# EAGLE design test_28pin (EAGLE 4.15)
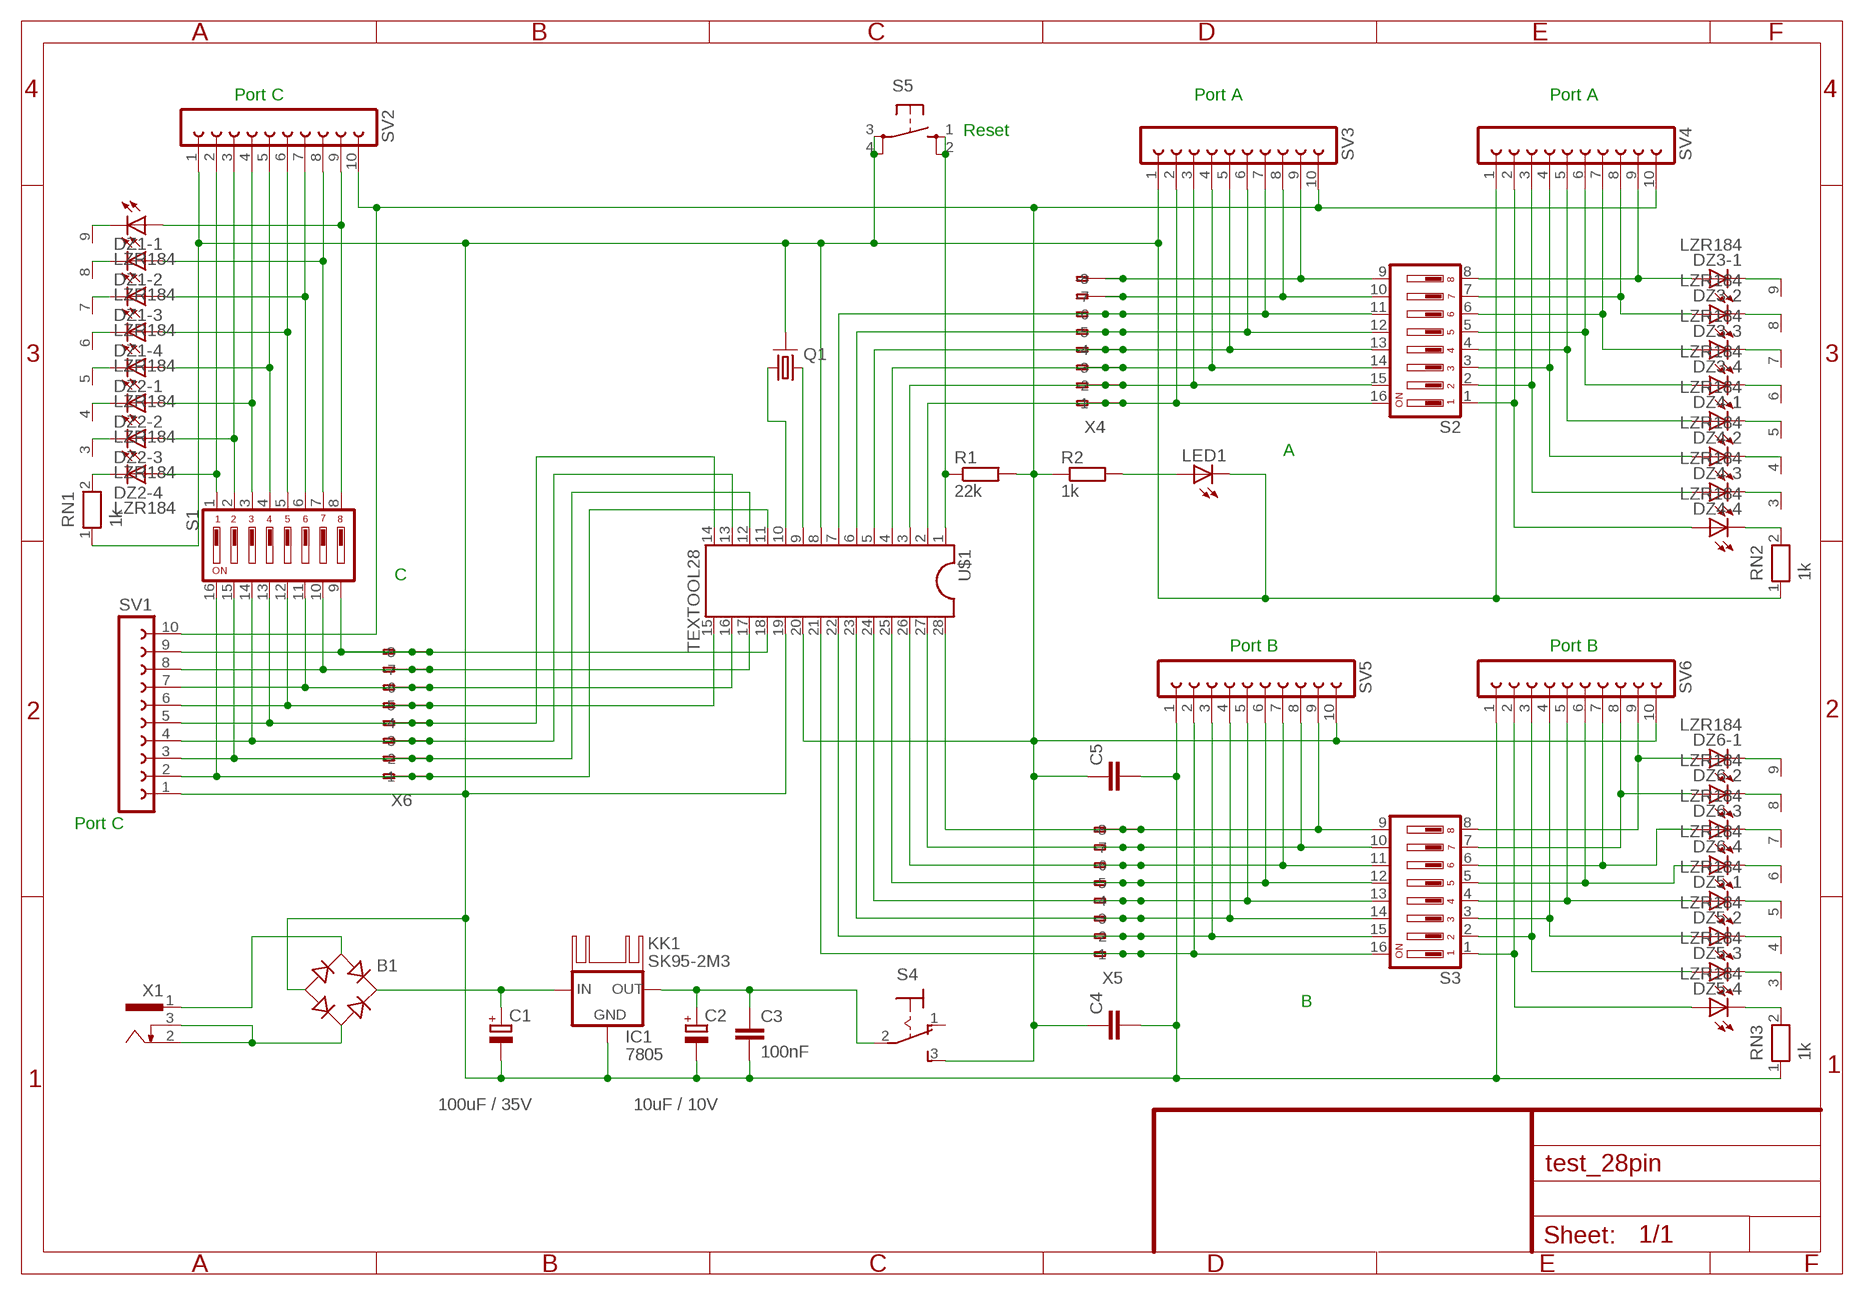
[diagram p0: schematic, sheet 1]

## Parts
B1  RB1A  [RB1A]
C1  100uF / 35V  CPOL-EUE2.5-5  [E2,5-5]
C2  10uF / 10V  CPOL-EUE2.5-5  [E2,5-5]
C3  100nF  C-EU025-024X044  [C025-024X044]
C4  C-EU050-025X075  [C050-025X075]
C5  C-EU050-025X075  [C050-025X075]
DZ1  LZR184  [LZR184]
DZ2  LZR184  [LZR184]
DZ3  LZR184  [LZR184]
DZ4  LZR184  [LZR184]
DZ5  LZR184  [LZR184]
DZ6  LZR184  [LZR184]
IC1  7805  78XXS  [78XXS]
KK1  SK95-2M3  [SK95-2M3]
LED1  LED3MM  [LED3MM]
Q1  RESONATOR  [RES3PIN]
R1  22k  R-EU_0207/15  [0207/15]
R2  1k  R-EU_0207/10  [0207/10]
RN1  1k  RN08  [RN-9]
RN2  1k  RN08  [RN-9]
RN3  1k  RN08  [RN-9]
S1  DS08  [DS-08]
S2  DS08  [DS-08]
S3  DS08  [DS-08]
S4  320-916  [320-916]
S5  10XX  [B3F-10XX]
SV1  FE10-1  [FE10]
SV2  FE10-1  [FE10]
SV3  FE10-1  [FE10]
SV4  FE10-1  [FE10]
SV5  FE10-1  [FE10]
SV6  FE10-1  [FE10]
U$1  TEXTOOL28  [TEXTOOL28]
X1  733989-55  [733989-5]
X4  233-508  [233-508]
X5  233-508  [233-508]
X6  233-508  [233-508]

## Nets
N$1: S3.16 SV5.2 U$1.21 X5.A1(-1) X5.B1(B-1)
N$2: S3.15 SV5.3 U$1.22 X5.A2(-2) X5.B2(B-2)
N$3: S3.14 SV5.4 U$1.23 X5.A3(-3) X5.B3(B-3)
N$4: S3.13 SV5.5 U$1.24 X5.A4(-4) X5.B4(B-4)
N$5: S3.12 SV5.6 U$1.25 X5.A5(-5) X5.B5(B-5)
N$6: S3.11 SV5.7 U$1.26 X5.A6(-6) X5.B6(B-6)
N$7: S3.10 SV5.8 U$1.27 X5.A7(-7) X5.B7(B-7)
N$8: S3.9 SV5.9 U$1.28 X5.A8(-8) X5.B8(B-8)
N$9: DZ6.A1(-1:A) S3.8 SV6.9
N$10: DZ6.A2(-2:A) S3.7 SV6.8
N$11: DZ6.A3(-3:A) S3.6 SV6.7
N$12: DZ6.A4(-4:A) S3.5 SV6.6
N$13: DZ5.A1(-1:A) S3.4 SV6.5
N$14: DZ5.A2(-2:A) S3.3 SV6.4
N$15: DZ5.A3(-3:A) S3.2 SV6.3
N$16: DZ5.A4(-4:A) S3.1 SV6.2
N$17: DZ6.K4(-4:C) RN3.6
N$18: DZ6.K1(-1:C) RN3.9
N$19: DZ6.K2(-2:C) RN3.8
N$20: DZ6.K3(-3:C) RN3.7
N$21: DZ5.K4(-4:C) RN3.2
N$22: DZ5.K1(-1:C) RN3.5
N$23: DZ5.K2(-2:C) RN3.4
N$24: DZ5.K3(-3:C) RN3.3
N$25: C4.1 C5.1 R1.2 R2.1 S4.3(S) SV1.10 SV2.10 SV3.10 SV4.10 SV5.10 SV6.10 U$1.20
N$26: LED1.A R2.2
N$27: DZ3.K1(-1:C) RN2.9
N$28: DZ3.K2(-2:C) RN2.8
N$29: DZ3.K3(-3:C) RN2.7
N$30: DZ3.K4(-4:C) RN2.6
N$31: DZ4.K1(-1:C) RN2.5
N$32: DZ4.K2(-2:C) RN2.4
N$33: DZ4.K3(-3:C) RN2.3
N$34: DZ4.K4(-4:C) RN2.2
N$35: S2.9 SV3.9 X4.A8(-8) X4.B8(B-8)
N$36: S2.10 SV3.8 X4.A7(-7) X4.B7(B-7)
N$37: S2.11 SV3.7 U$1.7 X4.A6(-6) X4.B6(B-6)
N$38: S2.12 SV3.6 U$1.6 X4.A5(-5) X4.B5(B-5)
N$39: S2.13 SV3.5 U$1.5 X4.A4(-4) X4.B4(B-4)
N$40: Q1.3 U$1.9
N$41: S2.15 SV3.3 U$1.3 X4.A2(-2) X4.B2(B-2)
N$42: S2.16 SV3.2 U$1.2 X4.A1(-1) X4.B1(B-1)
N$43: DZ4.A4(-4:A) S2.1 SV4.2
N$44: DZ4.A3(-3:A) S2.2 SV4.3
N$45: DZ4.A2(-2:A) S2.3 SV4.4
N$46: DZ4.A1(-1:A) S2.4 SV4.5
N$47: DZ3.A4(-4:A) S2.5 SV4.6
N$48: DZ3.A3(-3:A) S2.6 SV4.7
N$49: DZ3.A2(-2:A) S2.7 SV4.8
N$50: S1.9 SV1.9 U$1.18 X6.A8(-8) X6.B8(B-8)
N$51: DZ3.A1(-1:A) S2.8 SV4.9
N$54: DZ1.K1(-1:C) RN1.9
N$55: DZ1.K2(-2:C) RN1.8
N$56: DZ1.K3(-3:C) RN1.7
N$57: DZ1.K4(-4:C) RN1.6
N$58: DZ2.K1(-1:C) RN1.5
N$59: DZ2.K2(-2:C) RN1.4
N$60: DZ2.K3(-3:C) RN1.3
N$61: DZ2.K4(-4:C) RN1.2
N$62: DZ1.A1(-1:A) S1.8 SV2.9
N$63: DZ1.A2(-2:A) S1.7 SV2.8
N$64: DZ1.A3(-3:A) S1.6 SV2.7
N$65: DZ1.A4(-4:A) S1.5 SV2.6
N$66: DZ2.A1(-1:A) S1.4 SV2.5
N$67: DZ2.A2(-2:A) S1.3 SV2.4
N$68: DZ2.A3(-3:A) S1.2 SV2.3
N$69: DZ2.A4(-4:A) S1.1 SV2.2
N$70: S1.10 SV1.8 U$1.17 X6.A7(-7) X6.B7(B-7)
N$71: S1.11 SV1.7 U$1.16 X6.A6(-6) X6.B6(B-6)
N$72: S1.12 SV1.6 U$1.15 X6.A5(-5) X6.B5(B-5)
N$73: S1.13 SV1.5 U$1.14 X6.A4(-4) X6.B4(B-4)
N$74: S1.14 SV1.4 U$1.13 X6.A3(-3) X6.B3(B-3)
N$75: S1.15 SV1.3 U$1.12 X6.A2(-2) X6.B2(B-2)
N$76: S1.16 SV1.2 U$1.11 X6.A1(-1) X6.B1(B-1)
N$77: Q1.1 U$1.10
N$78: S2.14 SV3.4 U$1.4 X4.A3(-3) X4.B3(B-3)
N$81: B1.+ C1.+ IC1.IN
N$84: B1.AC2 X1.2 X1.3
N$85: B1.AC1 X1.1
N$86: R1.1 S5.1 S5.2 U$1.1
N$88: C2.+ C3.1 IC1.OUT S4.2(P)
VSS: B1.- C1.- C2.- C3.2 C4.2 C5.2 IC1.GND LED1.K(C) Q1.2 RN1.1 RN2.1 RN3.1 S5.3 S5.4 SV1.1 SV2.1 SV3.1 SV4.1 SV5.1 SV6.1 U$1.8 U$1.19
Unconnected: S4.1(O)

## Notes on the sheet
- Port C | Port A | Port A
- Reset
- A
- C
- Port B | Port B
- Port C
- B

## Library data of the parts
B1 = rectifier:RB1A: RECTIFIER 1 A
C1 C2 = rcl:CPOL-EU: POLARIZED CAPACITOR, European symbol
C3-C5 = rcl:C-EU: CAPACITOR, European symbol
DZ1-DZ6 = led:LZR184: LED BLOCK 4 LEDs, Siemens
IC1 = v-reg:78XXS: VOLTAGE REGULATOR
KK1 = heatsink:SK95-2M3: HEATSINK
LED1 = led:LED: LED
Q1 = sprut:RESONATOR: CRYSTAL
R1 R2 = rcl:R-EU_: RESISTOR, European symbol
RN1-RN3 = resistor-net:RN08: RESISTOR NETWORK
S1-S3 = switch-dil:DS08: DIL/CODE SWITCH
S4 = switch:320-916: TOGGLE SWITCH distributor RS Components
S5 = KEY_B:10XX
SV1-SV6 = con-lsta:FE10-1: FEMALE HEADER
U$1 = sprut:TEXTOOL28
X1 = con-conrad:733989-55: FEMALE PRINT CONNECTOR Außen-Ø 4,2 mm, Innen 1.1 mm FUK HING Industries, distributor Conrad
X4-X6 = con-wago:233-508: WAGO Cage Clamp

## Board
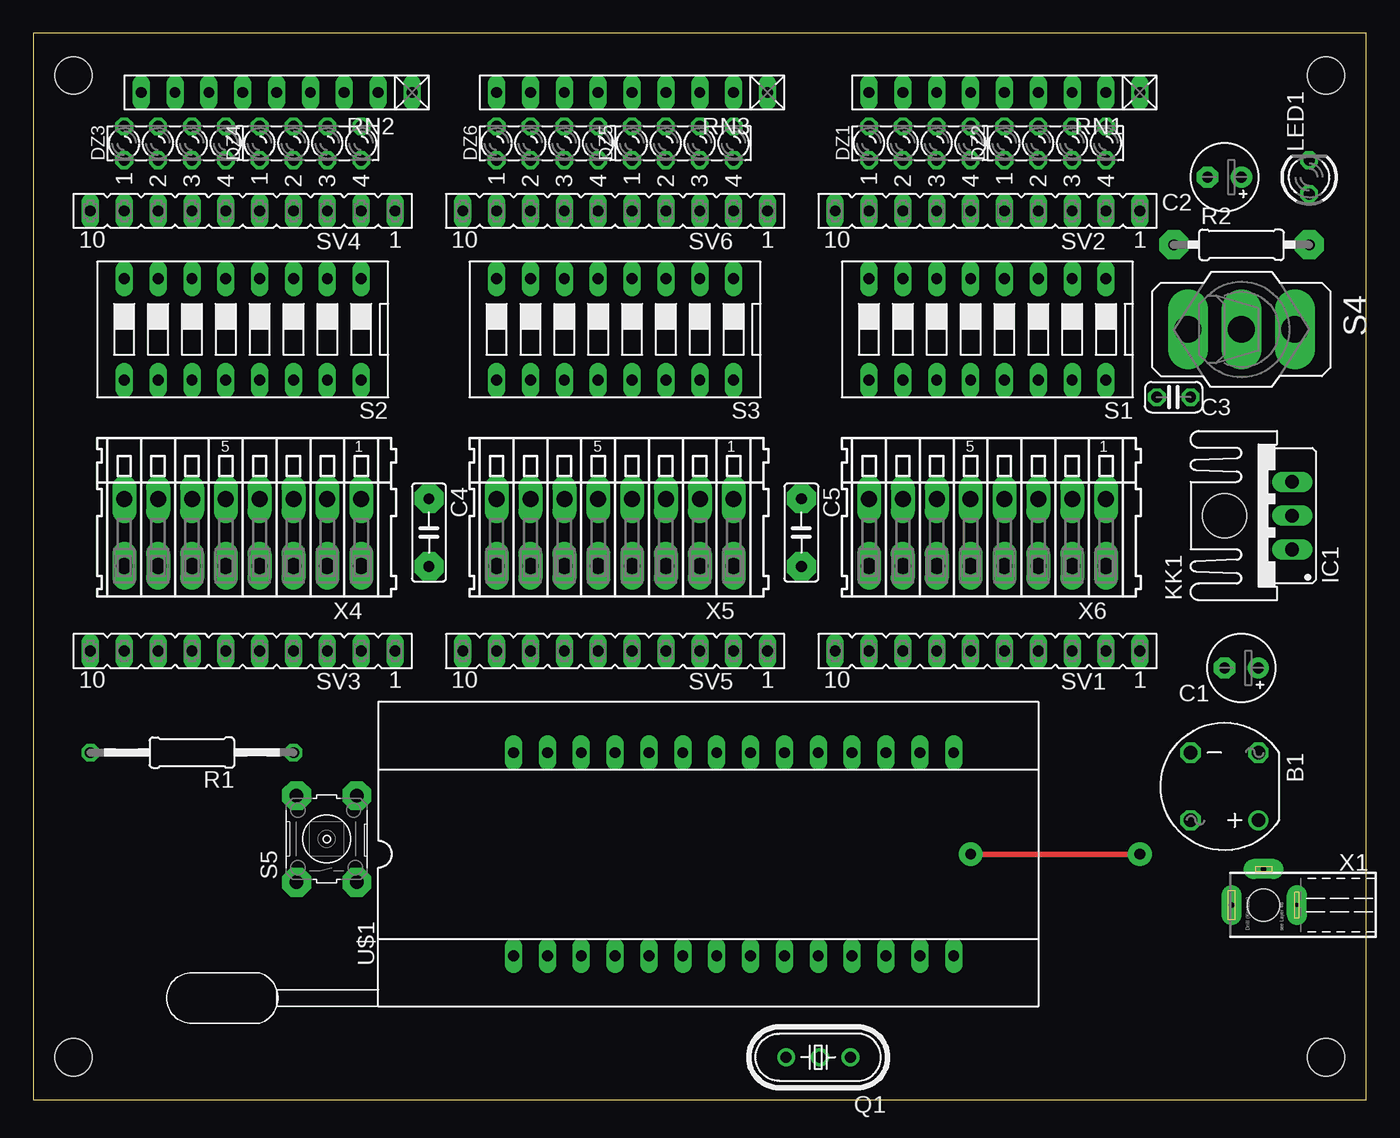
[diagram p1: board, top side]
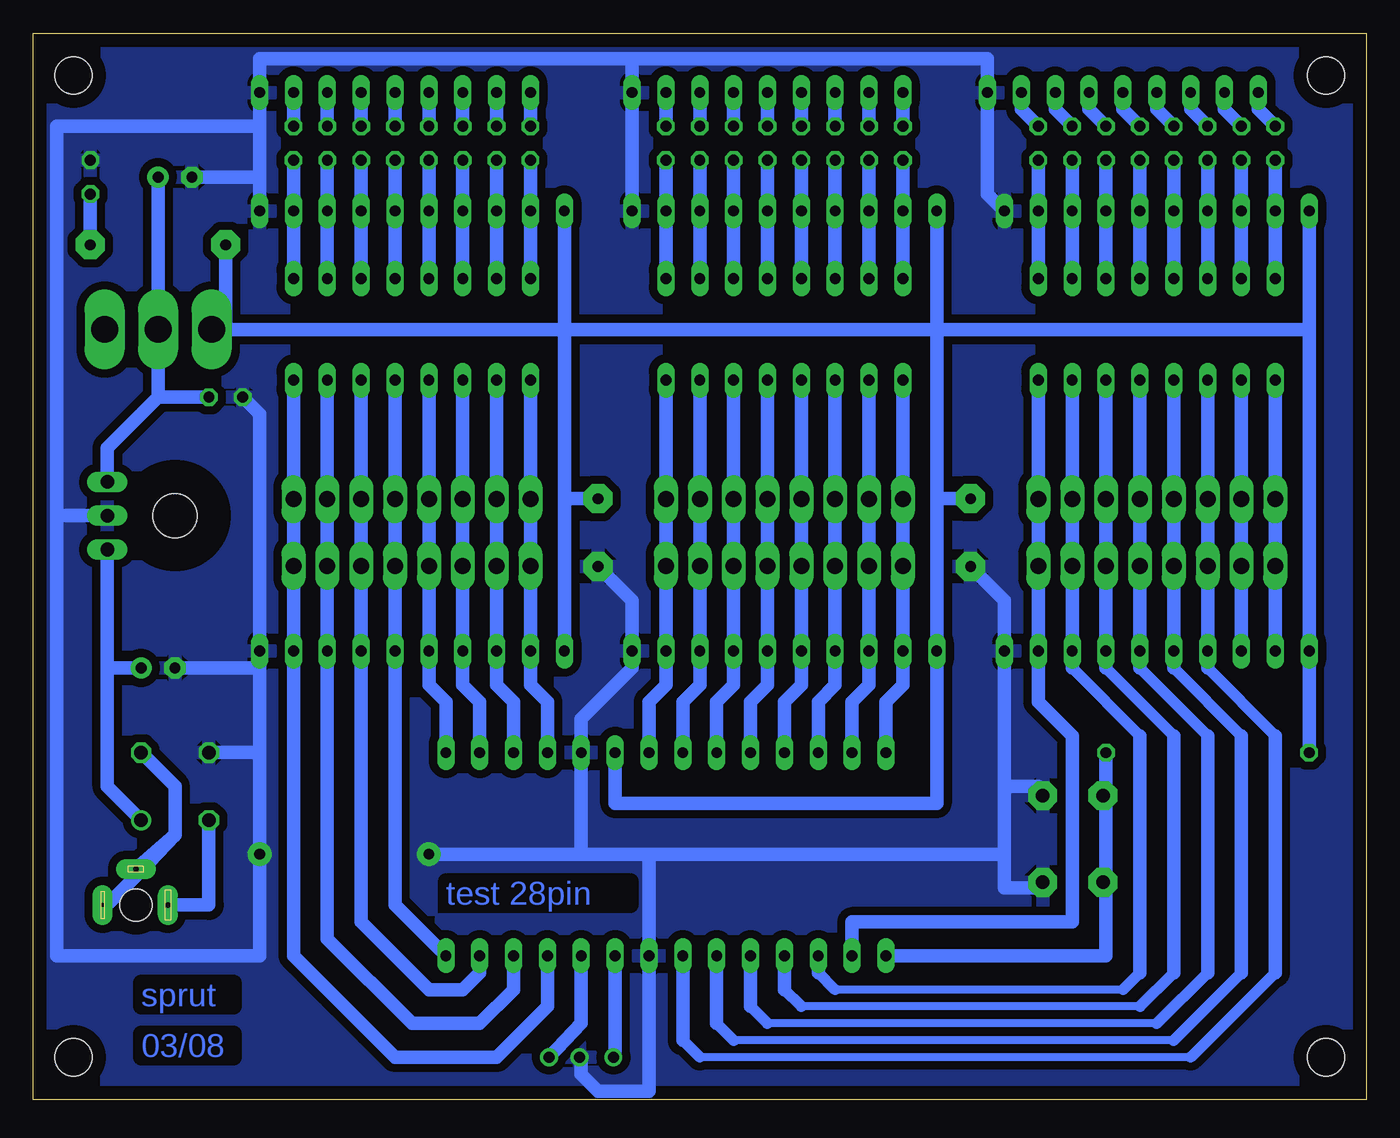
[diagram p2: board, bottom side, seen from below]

Size 100 x 80 mm. Coordinates in mm from the lower left corner, seen from the top.
Outline: 0,0 100,0 100,80 0,80 0,0
Copper layers (1*16): Top 0.035mm / dielectric 1.5mm / Bottom 0.035mm
Design rules "default": minimum track width 10mil, minimum drill 24mil, track to track 8mil, track to pad 8mil, pad to pad 8mil, via to via 8mil, smd to smd 8mil, copper to edge 40mil, drill to drill 8mil, minimum pad ring 10mil, minimum via ring 8mil, stop-mask expansion 4mil, vias tented up to drill 0mil, thermal gap 10mil
Holes 2.8 mm at 3.01,76.83 96.99,76.83 96.99,3.17 3.01,3.17

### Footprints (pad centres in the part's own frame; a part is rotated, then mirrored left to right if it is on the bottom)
RB1A = drill 1.016 round: + -2.54,2.54 | drill 1.016 octagon: - 2.54,-2.54; AC1 2.54,2.54; AC2 -2.54,-2.54
E2,5-5 = drill 0.813 pad 1.6 round: + -1.27,0 | drill 0.813 pad 1.6 octagon: - 1.27,0
C025-024X044 = drill 0.813 octagon: 1 -1.27,0; 2 1.27,0
C050-025X075 = drill 0.813 pad 2.184 octagon: 1 -2.54,0; 2 2.54,0
LZR184 = drill 0.813 octagon: A1 -1.27,3.81; A2 -1.27,1.27; A3 -1.27,-1.27; A4 -1.27,-3.81; K1 1.27,3.81; K2 1.27,1.27; K3 1.27,-1.27; K4 1.27,-3.81
78XXS = drill 1.016 long: GND 0,-2.54; IN -2.54,-2.54; OUT 2.54,-2.54
SK95-2M3 = hole 3.302: 0,2.54
LED3MM = drill 0.813 octagon: A -1.27,0; K 1.27,0
RES3PIN = drill 0.813 round: 1 -2.413,0; 2 -0.127,0; 3 2.413,0
0207/15 = drill 0.813 octagon: 1 -7.62,0; 2 7.62,0
0207/10 = drill 0.813 pad 2.184 octagon: 1 -5.08,0; 2 5.08,0
RN-9 = drill 0.813 long: 1 -10.16,0; 2 -7.62,0; 3 -5.08,0; 4 -2.54,0; 5 0,0; 6 2.54,0; 7 5.08,0; 8 7.62,0; 9 10.16,0
DS-08 = drill 0.813 long: 1 -8.89,-3.81; 2 -6.35,-3.81; 3 -3.81,-3.81; 4 -1.27,-3.81; 5 1.27,-3.81; 6 3.81,-3.81; 7 6.35,-3.81; 8 8.89,-3.81; 9 8.89,3.81; 10 6.35,3.81; 11 3.81,3.81; 12 1.27,3.81; 13 -1.27,3.81; 14 -3.81,3.81; 15 -6.35,3.81; 16 -8.89,3.81
320-916 = drill 2.007 long: 1 0,4.013; 2 0,0; 3 0,-4.013
B3F-10XX = drill 1.016 pad 2.159 octagon: 1 -3.379,2.312; 2 3.123,2.312; 3 -3.379,-2.209; 4 3.123,-2.209
FE10 = drill 0.813 long: 1 -11.43,0; 2 -8.89,0; 3 -6.35,0; 4 -3.81,0; 5 -1.27,0; 6 1.27,0; 7 3.81,0; 8 6.35,0; 9 8.89,0; 10 11.43,0
TEXTOOL28 = drill 0.813 long: 1 -16.51,-7.62; 2 -13.97,-7.62; 3 -11.43,-7.62; 4 -8.89,-7.62; 5 -6.35,-7.62; 6 -3.81,-7.62; 7 -1.27,-7.62; 8 1.27,-7.62; 9 3.81,-7.62; 10 6.35,-7.62; 11 8.89,-7.62; 12 11.43,-7.62; 13 13.97,-7.62; 14 16.51,-7.62; 15 16.51,7.62; 16 13.97,7.62; 17 11.43,7.62; 18 8.89,7.62; 19 6.35,7.62; 20 3.81,7.62; 21 1.27,7.62; 22 -1.27,7.62; 23 -3.81,7.62; 24 -6.35,7.62; 25 -8.89,7.62; 26 -11.43,7.62; 27 -13.97,7.62; 28 -16.51,7.62
733989-5 = drill 0.4 pad 1.5 long: 1 0,5.82; 3 2.7,3.42 | drill 0.3 pad 1.5 long: 2 0,0.92 | hole 2.4: 0,3.42
233-508 = drill 1.2 long: A1 -8.89,2.5; A2 -6.35,2.5; A3 -3.81,2.5; A4 -1.27,2.5; A5 1.27,2.5; A6 3.81,2.5; A7 6.35,2.5; A8 8.89,2.5; B1 -8.89,-2.5; B2 -6.35,-2.5; B3 -3.81,-2.5; B4 -1.27,-2.5; B5 1.27,-2.5; B6 3.81,-2.5; B7 6.35,-2.5; B8 8.89,-2.5

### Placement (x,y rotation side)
B1  89.37,23.49 180 top
C1  90.64,32.38 180 top
C2  89.37,69.21 180 top
C3  85.56,52.7 180 top
C4  29.68,42.54 270 top
C5  57.62,42.54 270 top
DZ1  66.51,71.75 90 top
DZ2  76.67,71.75 90 top
DZ3  10.63,71.75 90 top
DZ4  20.79,71.75 90 top
DZ5  48.73,71.75 90 top
DZ6  38.57,71.75 90 top
IC1  91.91,43.81 90 top
KK1  91.91,43.81 90 top
LED1  95.72,69.21 90 top
Q1  58.89,3.17 180 top
R1  11.9,26.03 180 top
R2  90.64,64.13 0 top
RN1  72.86,75.56 180 top
RN2  18.25,75.56 180 top
RN3  44.92,75.56 180 top
S1  71.59,57.78 180 top
S2  15.71,57.78 180 top
S3  43.65,57.78 180 top
S4  90.64,57.78 270 top
S5  22.06,19.68 90 top
SV1  71.59,33.65 180 top
SV2  71.59,66.67 180 top
SV3  15.71,33.65 180 top
SV4  15.71,66.67 180 top
SV5  43.65,33.65 180 top
SV6  43.65,66.67 180 top
U$1  52.54,18.41 0 top
X1  95.72,14.6 90 top
X4  15.71,42.54 180 top
X5  43.65,42.54 180 top
X6  71.59,42.54 180 top

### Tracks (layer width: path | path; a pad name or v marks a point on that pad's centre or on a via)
N$1
  Bottom 1.016: U$1.21 53.81,29.84 52.54,31.11 SV5.2 X5.A1 | S3.16 X5.B1 X5.A1 | X5.A1 52.54,40
N$2
  Bottom 1.016: U$1.22 51.27,29.84 50,31.11 SV5.3 X5.A2 X5.B2 | X5.B2 50,45.08 | X5.B2 S3.15
N$3
  Bottom 1.016: U$1.23 48.73,29.84 47.46,31.11 SV5.4 X5.A3 | S3.14 X5.B3 X5.A3 | X5.A3 47.46,40
N$4
  Bottom 1.016: U$1.24 46.19,29.84 44.92,31.11 SV5.5 X5.A4 X5.B4 | X5.B4 44.92,45.08 | X5.B4 S3.13
N$5
  Bottom 1.016: U$1.25 43.65,29.84 42.38,31.11 SV5.6 X5.A5 | S3.12 X5.B5 X5.A5 | X5.A5 42.38,40
N$6
  Bottom 1.016: U$1.26 41.11,29.84 39.84,31.11 SV5.7 X5.A6 X5.B6 | X5.B6 39.84,45.08 | X5.B6 S3.11
N$7
  Bottom 0.406: X5.B7 37.3,45.08
  Bottom 1.016: U$1.27 38.57,29.84 37.3,31.11 SV5.8 X5.A7 X5.B7 S3.10
N$8
  Bottom 0.406: X5.A8 34.76,40
  Bottom 1.016: U$1.28 36.03,29.84 34.76,31.11 SV5.9 X5.A8 X5.B8 S3.9
N$9
  Bottom 1.016: DZ6.A1 SV6.9 S3.8
N$10
  Bottom 1.016: DZ6.A2 SV6.8 S3.7
N$11
  Bottom 1.016: DZ6.A3 SV6.7 S3.6
N$12
  Bottom 1.016: S3.5 SV6.6 DZ6.A4
N$13
  Bottom 1.016: DZ5.A1 SV6.5 S3.4
N$14
  Bottom 1.016: S3.3 SV6.4 DZ5.A2
N$15
  Bottom 1.016: S3.2 SV6.3 DZ5.A3
N$16
  Bottom 1.016: DZ5.A4 SV6.2 S3.1
N$17
  Bottom 1.016: DZ6.K4 RN3.6
N$18
  Bottom 1.016: DZ6.K1 RN3.9
N$19
  Bottom 1.016: DZ6.K2 RN3.8
N$20
  Bottom 1.016: DZ6.K3 RN3.7
N$21
  Bottom 1.016: DZ5.K4 RN3.2
N$22
  Bottom 1.016: DZ5.K1 RN3.5
N$23
  Bottom 1.016: DZ5.K2 RN3.4
N$24
  Bottom 1.016: DZ5.K3 RN3.3
N$25
  Bottom 1.016: R1.2 SV3.10 4.28,57.78 | 32.22,57.78 32.22,45.08 | 32.22,45.08 SV5.10 32.22,22.22 56.35,22.22 U$1.20 | 32.22,57.78 SV6.10 | 60.16,57.78 SV2.10 | 60.16,57.78 60.16,45.08 | 60.16,45.08 SV1.10 | 32.22,57.78 60.16,57.78 | 4.28,57.78 SV4.10 | 4.28,57.78 32.22,57.78 | 32.22,45.08 C4.1 | 60.16,45.08 C5.1 | 60.16,57.78 85.56,57.78 | 85.56,57.78 S4.3 | 85.56,57.78 R2.1
N$26
  Bottom 1.016: R2.2 LED1.A
N$27
  Bottom 1.016: DZ3.K1 8.09,74.29 RN2.9
N$28
  Bottom 1.016: DZ3.K2 10.63,74.29 RN2.8
N$29
  Bottom 1.016: DZ3.K3 13.17,74.29 RN2.7
N$30
  Bottom 1.016: DZ3.K4 15.71,74.29 RN2.6
N$31
  Bottom 1.016: DZ4.K1 18.25,74.29 RN2.5
N$32
  Bottom 1.016: DZ4.K2 20.79,74.29 RN2.4
N$33
  Bottom 1.016: DZ4.K3 23.33,74.29 RN2.3
N$34
  Bottom 1.016: DZ4.K4 25.87,74.29 RN2.2
N$35
  Bottom 1.016: 6.82,45.08 S2.9 | SV3.9 X4.A8 6.82,45.08 | 6.82,45.08 X4.B8
N$36
  Bottom 1.016: 9.36,45.08 S2.10 | SV3.8 X4.A7 9.36,45.08 | 9.36,45.08 X4.B7
N$37
  Bottom 0.61: 13.17,3.17 50,3.17
  Bottom 0.813: 6.82,9.52 13.17,3.17 | 50,3.17 51.27,4.44 | 6.82,27.3 11.9,32.38
  Bottom 1.016: 51.27,4.44 U$1.7 | 6.82,9.52 6.82,27.3 | 11.9,32.38 SV3.7 X4.A6 X4.B6 | X4.B6 11.9,45.08 | X4.B6 S2.11
N$38
  Bottom 0.61: 14.44,4.44 47.46,4.44
  Bottom 0.813: 9.36,27.3 14.44,32.38 | 14.44,4.44 9.36,9.52 | 47.46,4.44 48.73,5.71
  Bottom 1.016: 9.36,9.52 9.36,27.3 | 14.44,32.38 SV3.6 X4.A5 | 48.73,5.71 U$1.6 | S2.12 X4.B5 X4.A5 | X4.A5 14.44,40
N$39
  Bottom 0.61: 15.71,5.71 44.92,5.71
  Bottom 0.813: 11.9,9.52 15.71,5.71 | 44.92,5.71 46.19,6.98 | 11.9,27.3 16.98,32.38
  Bottom 1.016: 46.19,6.98 U$1.5 | 11.9,9.52 11.9,27.3 | 16.98,32.38 SV3.5 X4.A4 X4.B4 | X4.B4 16.98,45.08 | X4.B4 S2.13
N$40
  Bottom 1.016: U$1.9 56.35,3.17 Q1.3
N$41
  Bottom 0.406: X4.A2 22.06,40
  Bottom 0.61: 18.25,8.25 39.84,8.25
  Bottom 0.813: 16.98,9.52 18.25,8.25 | 39.84,8.25 41.11,9.52 | 16.98,27.3 22.06,32.38
  Bottom 1.016: 41.11,9.52 U$1.3 | 16.98,9.52 16.98,27.3 | 22.06,32.38 SV3.3 X4.A2 X4.B2 S2.15
N$42
  Bottom 0.406: X4.B1 24.6,45.08
  Bottom 1.016: U$1.2 38.57,13.33 22.06,13.33 22.06,27.3 24.6,29.84 SV3.2 X4.A1 X4.B1 S2.16
N$43
  Bottom 1.016: S2.1 SV4.2 DZ4.A4
N$44
  Bottom 1.016: S2.2 SV4.3 DZ4.A3
N$45
  Bottom 1.016: DZ4.A2 SV4.4 S2.3
N$46
  Bottom 1.016: S2.4 SV4.5 DZ4.A1
N$47
  Bottom 1.016: DZ3.A4 SV4.6 S2.5
N$48
  Bottom 1.016: S2.6 SV4.7 DZ3.A3
N$49
  Bottom 1.016: S2.7 SV4.8 DZ3.A2
N$50
  Bottom 1.016: U$1.18 61.43,29.84 62.7,31.11 SV1.9 X6.A8 X6.B8 | X6.B8 62.7,45.08 | X6.B8 S1.9
N$51
  Bottom 1.016: DZ3.A1 SV4.9 S2.8
N$54
  Bottom 1.016: DZ1.K1 RN1.9
N$55
  Bottom 1.016: DZ1.K2 RN1.8
N$56
  Bottom 1.016: DZ1.K3 RN1.7
N$57
  Bottom 1.016: DZ1.K4 RN1.6
N$58
  Bottom 1.016: DZ2.K1 RN1.5
N$59
  Bottom 1.016: DZ2.K2 RN1.4
N$60
  Bottom 1.016: DZ2.K3 RN1.3
N$61
  Bottom 1.016: DZ2.K4 RN1.2
N$62
  Bottom 1.016: S1.8 SV2.9 DZ1.A1
N$63
  Bottom 1.016: DZ1.A2 SV2.8 S1.7
N$64
  Bottom 1.016: S1.6 SV2.7 DZ1.A3
N$65
  Bottom 1.016: DZ1.A4 SV2.6 S1.5
N$66
  Bottom 1.016: S1.4 SV2.5 DZ2.A1
N$67
  Bottom 1.016: DZ2.A2 SV2.4 S1.3
N$68
  Bottom 1.016: DZ2.A3 SV2.3 S1.2
N$69
  Bottom 1.016: DZ2.A4 SV2.2 S1.1
N$70
  Bottom 1.016: U$1.17 63.97,29.84 65.24,31.11 SV1.8 X6.A7 | S1.10 X6.B7 X6.A7 | X6.A7 65.24,40
N$71
  Bottom 1.016: U$1.16 66.51,29.84 67.78,31.11 SV1.7 X6.A6 X6.B6 | X6.B6 67.78,45.08 | X6.B6 S1.11
N$72
  Bottom 1.016: U$1.15 69.05,29.84 70.32,31.11 SV1.6 X6.A5 | S1.12 X6.B5 X6.A5 | X6.A5 70.32,40
N$73
  Bottom 1.016: U$1.14 72.86,14.6 SV1.5 X6.A4 X6.B4 | X6.B4 72.86,45.08 | X6.B4 S1.13
N$74
  Bottom 1.016: U$1.13 66.51,9.52 67.78,8.25 70.32,8.25 75.4,13.33 SV1.4 X6.A3 | S1.14 X6.B3 X6.A3 | X6.A3 75.4,40
N$75
  Bottom 1.016: U$1.12 63.97,8.25 66.51,5.71 71.59,5.71 77.94,12.06 SV1.3 X6.A2 77.94,45.08 | 77.94,45.08 S1.15 | 77.94,41.27 X6.B2 77.94,45.08
N$76
  Bottom 1.016: U$1.11 61.43,6.98 65.24,3.17 72.86,3.17 80.48,10.79 SV1.2 X6.A1 80.48,45.08 | 80.48,45.08 S1.16 | 80.48,45.08 X6.B1
N$77
  Bottom 1.016: Q1.1 58.89,5.71 U$1.10
N$78
  Bottom 0.61: 16.98,6.98 42.38,6.98
  Bottom 0.813: 14.44,27.3 19.52,32.38 | 16.98,6.98 14.44,9.52 | 42.38,6.98 43.65,8.25
  Bottom 1.016: 19.52,32.38 SV3.4 X4.A3 | 14.44,9.52 14.44,27.3 | 43.65,8.25 U$1.4 | S2.14 X4.B3 X4.A3 | X4.A3 19.52,40
N$81
  Bottom 1.016: 94.45,32.38 C1.+ | B1.+ 94.45,23.49 94.45,32.38 | 94.45,32.38 IC1.IN
N$84
  Bottom 1.016: 91.91,17.14 89.37,19.84 | 89.37,19.84 X1.3 92.07,17.3 91.91,17.14 | 89.37,19.84 89.37,23.49 B1.AC2 | X1.2 94.45,14.6 91.91,17.14
N$85
  Bottom 1.016: B1.AC1 86.83,14.6 X1.1
N$86
  Bottom 0.406: S5.2 19.75,22.45 19.52,22.22 | S5.1 19.75,16.1 19.52,15.87
  Bottom 1.016: R1.1 19.52,22.22 19.52,15.87 19.52,10.79 U$1.1
N$88
  Bottom 1.016: 90.64,52.7 94.45,48.89 IC1.OUT | C3.1 90.64,52.7 | 90.64,52.7 S4.2 C2.+
VSS  (via drill 0.8 pad 1.78)
  Top 0.406: v70.32,18.41 v83.02,18.41
  Bottom 0.406: 24.6,23.49 24.27,23.16
  Bottom 0.61: 58.89,3.17 Q1.2
  Bottom 1.016: 27.14,18.41 27.14,15.87 24.6,15.87 24.27,16.2 S5.3 | 27.14,18.41 27.14,23.49 | 27.14,23.49 SV3.1 27.14,37.46 C4.2 | 24.27,23.16 S5.4 | 27.14,23.49 24.6,23.49 | SV6.1 RN3.1 55.08,78.1 | 83.02,73.02 RN1.1 83.02,78.1 55.08,78.1 | 83.02,73.02 SV2.1 83.02,69.21 C2.- | 55.08,78.1 28.41,78.1 RN2.1 28.41,67.94 SV4.1 | 58.89,18.41 U$1.19 58.89,28.57 55.08,32.38 SV5.1 55.08,37.46 C5.2 | 27.14,18.41 53.81,18.41 | 53.81,18.41 58.89,18.41 | 53.81,18.41 U$1.8 53.81,0.63 57.62,0.63 58.89,1.9 58.89,3.17 | C3.2 83.02,51.43 83.02,32.38 | 83.02,32.38 C1.- | 83.02,26.03 B1.- | 83.02,26.03 v83.02,18.41 83.02,10.79 98.26,10.79 98.26,43.81 | 83.02,26.03 83.02,32.38 | 83.02,32.38 SV1.1 | 58.89,18.41 v70.32,18.41 | 98.26,43.81 98.26,73.02 83.02,73.02 | 98.26,43.81 IC1.GND
  pour Bottom (isolate 0.61): -0.8,80.64 100.8,80.64 100.8,-0.64 -0.8,-0.64

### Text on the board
Bottom: test 28pin | sprut | 03/08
